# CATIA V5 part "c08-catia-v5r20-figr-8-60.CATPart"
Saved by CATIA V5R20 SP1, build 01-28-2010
Part number: Part1
Bounding box of the stored display mesh (mm): x -50.499 to 50.499, y -68.48 to 68.48, z 0 to 20
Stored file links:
  D:\v5_r20\psrt_files_downloaded\c08-catia-v5r20-prt\c08-catia-v5r20-figr-8-60.CATPart
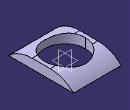
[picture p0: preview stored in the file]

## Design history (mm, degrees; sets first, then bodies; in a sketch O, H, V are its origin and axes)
Body1 (main body)
  Sketch1 on xy-plane, origin (0, 0, 0), H (1, 0, 0), V (0, 1, 0)
    line L1 (-50.499, 68.4797) -> (50.499, 68.4797)
    line L2 (50.499, 68.4797) -> (50.499, -68.4797)
    line L3 (50.499, -68.4797) -> (-50.499, -68.4797)
    line L4 (-50.499, -68.4797) -> (-50.499, 68.4797)
    axis line L5 (50.499, -68.4797) -> (-50.499, 68.4797)
    horizontal: L1 H, L3 H
    vertical: L2 V, L4 V
    midpoint: O L5
  Pad1: profile Sketch1, direction (0, 0, 1), length 20
  Fillet1: radius 71, on edge [face of Pad1 | face of Pad1]
  Fillet2: radius 71, on edge [face of Pad1 | face of Pad1]
  Body2
    Sketch2 on xy-plane, origin (0, 0, 0), H (1, 0, 0), V (0, 1, 0)
      circle A1 centre (0, 0) radius 43.2524
      point P1 (0, 43.2524)
      coincidence: A1 P1, P1 V
    Pocket1: profile Sketch2, direction (0, 0, -1), length 50, mirrored extent
  Assemble1: tool Body2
